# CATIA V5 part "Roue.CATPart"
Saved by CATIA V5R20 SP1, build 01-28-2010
Part number: Roue
Bounding box of the stored display mesh (mm): x 150.72 to 203.576, y 187.282 to 377.242, z -527.865 to -338.24
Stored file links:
  C:\Users\RENARD Simon\Documents\Cours IFMA\2ème année\IAO\Roue.CATPart
  C:\Users\RENARD Simon\Documents\Cours IFMA\2ème année\IAO\Trainattero.CATProduct
  C:\Users\RENARD Simon\Documents\Cours IFMA\2ème année\IAO\AxeR-1.CATPart
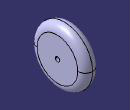
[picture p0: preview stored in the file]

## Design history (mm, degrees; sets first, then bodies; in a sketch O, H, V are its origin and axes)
Set1
  DatumSurface1: linked copy from another document
  DatumCurve1: linked copy from another document
Body1 (main body)
  Sketch1 on face of DatumSurface1, origin (196.2904, -4.02, 0), H (-0.0205, -0.9998, 0), V (0, 0, 1)
    circle A1 centre (-285.8299, -433.052) radius 95
    reference projected circle E1 centre (-285.8299, -433.052) radius 7.5 from edge of DatumCurve1
    circle A2 centre (-285.8299, -433.052) radius 7.5
    radius A1 = 95
    radius A2 = 7.5
    concentricity: E1 A1
  Pad1: profile Sketch1, direction (-0.9998, 0.0205, 0), length 50
  Fillet1: radius 25, on edge [face of Pad1 from Sketch1.A1 | end face of Pad1]
  Fillet2: radius 25, on edge [start face of Pad1 | face of Pad1 from Sketch1.A1]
